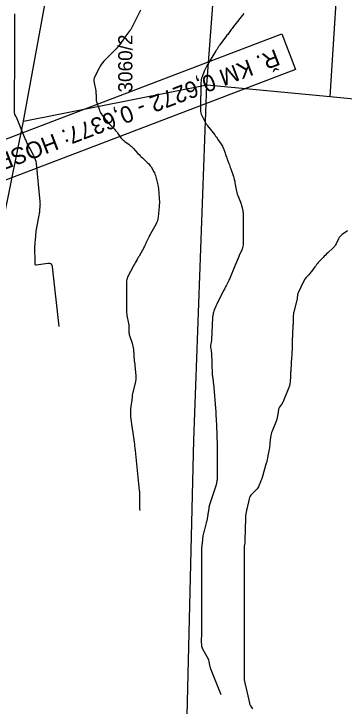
# Model space of a CAD drawing. Extents: x -534410 to -534262, y -1190162 to -1189584.
# Drawn here: x -534375.88 to -534356.09, y -1189988.43 to -1189946.91 of the extents above; entities that cross this region are included whole.
import ezdxf

# ---------------------------------------------------------------- set-up
doc = ezdxf.new("R2010")
doc.units = 0
for name, color, linetype in [('30', 7, 'Continuous'), ('31', 7, 'Continuous'), ('_N_text', 7, 'Continuous'), ('Hranice parcel', 7, 'Continuous'), ('Parcelní čísla', 7, 'Continuous')]:
    doc.layers.add(name, color=color, linetype=linetype)

msp = doc.modelspace()

# ---------------------------------------------------------------- linework, layer by layer
at = {"layer": '30'}
for points in [[(-534373.173, -1189965.667), (-534373.562, -1189962.09), (-534373.59, -1189961.98), (-534373.646, -1189961.907), (-534373.731, -1189961.871), (-534373.844, -1189961.871), (-534374.539, -1189961.971), (-534374.568, -1189961.971), (-534374.59, -1189961.962), (-534374.602, -1189961.942), (-534374.606, -1189961.913), (-534374.606, -1189961.776), (-534374.607, -1189961.742), (-534374.607, -1189961.708), (-534374.607, -1189961.674), (-534374.607, -1189961.64), (-534374.615, -1189961.047), (-534374.616, -1189960.946), (-534374.613, -1189960.845), (-534374.609, -1189960.743), (-534374.602, -1189960.642), (-534374.568, -1189960.238), (-534374.559, -1189960.137), (-534374.547, -1189960.036), (-534374.533, -1189959.936), (-534374.516, -1189959.836), (-534374.36, -1189958.978), (-534374.348, -1189958.911), (-534374.338, -1189958.844), (-534374.33, -1189958.777), (-534374.323, -1189958.709), (-534374.297, -1189958.438), (-534374.293, -1189958.371), (-534374.291, -1189958.303), (-534374.293, -1189958.235), (-534374.298, -1189958.168), (-534374.531, -1189955.886), (-534374.548, -1189955.772), (-534374.576, -1189955.662), (-534374.615, -1189955.556), (-534374.665, -1189955.453), (-534374.93, -1189954.968), (-534374.964, -1189954.906), (-534374.995, -1189954.843), (-534375.026, -1189954.78), (-534375.056, -1189954.716), (-534375.171, -1189954.458), (-534375.199, -1189954.394), (-534375.227, -1189954.329), (-534375.255, -1189954.264), (-534375.282, -1189954.199), (-534375.727, -1189953.111), (-534375.735, -1189953.092), (-534375.744, -1189953.072), (-534375.753, -1189953.054), (-534375.763, -1189953.035), (-534375.813, -1189952.942), (-534375.817, -1189952.933), (-534375.821, -1189952.923), (-534375.824, -1189952.914), (-534375.827, -1189952.904), (-534375.835, -1189952.864), (-534375.836, -1189952.854), (-534375.837, -1189952.844), (-534375.838, -1189952.834), (-534375.838, -1189952.824), (-534375.835, -1189952.777), (-534375.834, -1189952.765), (-534375.834, -1189952.754), (-534375.833, -1189952.743), (-534375.833, -1189952.732), (-534375.833, -1189950.957), (-534375.833, -1189950.946), (-534375.833, -1189950.935), (-534375.833, -1189950.924), (-534375.832, -1189950.912), (-534375.825, -1189950.784), (-534375.825, -1189950.773), (-534375.825, -1189950.763), (-534375.824, -1189950.753), (-534375.824, -1189950.743), (-534375.824, -1189948.946), (-534375.824, -1189948.936), (-534375.824, -1189948.926), (-534375.824, -1189948.916), (-534375.823, -1189948.905), (-534375.821, -1189948.863), (-534375.821, -1189948.844), (-534375.82, -1189948.826), (-534375.819, -1189948.778), (-534375.819, -1189948.759), (-534375.819, -1189948.75), (-534375.819, -1189946.939), (-534375.819, -1189946.92), (-534375.818, -1189946.901)], [(-534362.103, -1189946.892), (-534362.716, -1189947.667), (-534362.761, -1189947.724), (-534362.805, -1189947.782), (-534362.849, -1189947.841), (-534362.892, -1189947.899), (-534363.065, -1189948.135), (-534363.108, -1189948.194), (-534363.152, -1189948.253), (-534363.195, -1189948.312), (-534363.238, -1189948.37), (-534363.549, -1189948.789), (-534363.569, -1189948.817), (-534363.589, -1189948.845), (-534363.609, -1189948.873), (-534363.628, -1189948.902), (-534363.705, -1189949.016), (-534363.724, -1189949.045), (-534363.742, -1189949.073), (-534363.761, -1189949.103), (-534363.779, -1189949.132), (-534364.316, -1189950.027), (-534364.36, -1189950.104), (-534364.401, -1189950.183), (-534364.438, -1189950.264), (-534364.473, -1189950.346), (-534364.602, -1189950.678), (-534364.631, -1189950.762), (-534364.652, -1189950.848), (-534364.665, -1189950.934), (-534364.67, -1189951.023), (-534364.681, -1189951.753), (-534364.681, -1189951.768), (-534364.681, -1189951.782), (-534364.682, -1189951.797), (-534364.683, -1189951.812), (-534364.687, -1189951.87), (-534364.688, -1189951.884), (-534364.688, -1189951.899), (-534364.689, -1189951.913), (-534364.689, -1189951.928), (-534364.699, -1189952.666), (-534364.695, -1189952.754), (-534364.68, -1189952.84), (-534364.656, -1189952.923), (-534364.62, -1189953.003), (-534364.459, -1189953.321), (-534364.417, -1189953.399), (-534364.371, -1189953.475), (-534364.322, -1189953.549), (-534364.269, -1189953.621), (-534363.843, -1189954.172), (-534363.794, -1189954.237), (-534363.745, -1189954.303), (-534363.698, -1189954.37), (-534363.652, -1189954.437), (-534363.463, -1189954.719), (-534363.423, -1189954.783), (-534363.387, -1189954.849), (-534363.355, -1189954.917), (-534363.327, -1189954.987), (-534363.224, -1189955.272), (-534363.198, -1189955.344), (-534363.172, -1189955.415), (-534363.145, -1189955.486), (-534363.119, -1189955.557), (-534362.995, -1189955.881), (-534362.965, -1189955.959), (-534362.937, -1189956.037), (-534362.909, -1189956.116), (-534362.882, -1189956.194), (-534362.725, -1189956.655), (-534362.695, -1189956.75), (-534362.669, -1189956.846), (-534362.647, -1189956.944), (-534362.629, -1189957.042), (-534362.562, -1189957.449), (-534362.544, -1189957.54), (-534362.522, -1189957.63), (-534362.495, -1189957.719), (-534362.463, -1189957.807), (-534362.307, -1189958.205), (-534362.284, -1189958.267), (-534362.263, -1189958.33), (-534362.244, -1189958.394), (-534362.227, -1189958.458), (-534362.165, -1189958.716), (-534362.151, -1189958.78), (-534362.141, -1189958.845), (-534362.135, -1189958.911), (-534362.133, -1189958.977), (-534362.133, -1189960.661), (-534362.138, -1189960.752), (-534362.151, -1189960.841), (-534362.173, -1189960.928), (-534362.205, -1189961.014), (-534362.372, -1189961.408), (-534362.396, -1189961.465), (-534362.42, -1189961.521), (-534362.444, -1189961.577), (-534362.469, -1189961.634), (-534362.568, -1189961.858), (-534362.592, -1189961.915), (-534362.616, -1189961.971), (-534362.64, -1189962.028), (-534362.663, -1189962.085), (-534362.915, -1189962.711), (-534362.943, -1189962.778), (-534362.972, -1189962.843), (-534363.003, -1189962.908), (-534363.035, -1189962.972), (-534363.167, -1189963.227), (-534363.2, -1189963.29), (-534363.233, -1189963.354), (-534363.266, -1189963.418), (-534363.299, -1189963.482), (-534363.7, -1189964.269), (-534363.721, -1189964.311), (-534363.741, -1189964.354), (-534363.76, -1189964.397), (-534363.778, -1189964.441), (-534363.869, -1189964.67), (-534363.876, -1189964.688), (-534363.882, -1189964.705), (-534363.889, -1189964.722), (-534363.895, -1189964.74), (-534363.918, -1189964.81), (-534363.923, -1189964.827), (-534363.928, -1189964.845), (-534363.932, -1189964.863), (-534363.935, -1189964.881), (-534363.959, -1189965.014), (-534363.963, -1189965.042), (-534363.967, -1189965.07), (-534363.97, -1189965.099), (-534363.971, -1189965.127), (-534364.039, -1189966.468), (-534364.042, -1189966.506), (-534364.046, -1189966.544), (-534364.053, -1189966.582), (-534364.061, -1189966.62), (-534364.097, -1189966.77), (-534364.103, -1189966.807), (-534364.106, -1189966.845), (-534364.104, -1189966.882), (-534364.098, -1189966.92), (-534364.064, -1189967.073), (-534364.057, -1189967.111), (-534364.051, -1189967.149), (-534364.047, -1189967.188), (-534364.044, -1189967.227), (-534363.99, -1189968.538), (-534363.988, -1189968.569), (-534363.986, -1189968.6), (-534363.982, -1189968.631), (-534363.978, -1189968.661), (-534363.955, -1189968.798), (-534363.952, -1189968.821), (-534363.948, -1189968.845), (-534363.946, -1189968.868), (-534363.943, -1189968.891), (-534363.935, -1189968.985), (-534363.93, -1189969.032), (-534363.926, -1189969.079), (-534363.779, -1189970.793), (-534363.778, -1189970.802), (-534363.778, -1189970.81), (-534363.777, -1189970.819), (-534363.777, -1189970.828), (-534363.777, -1189970.862), (-534363.777, -1189970.87), (-534363.777, -1189970.879), (-534363.777, -1189970.887), (-534363.776, -1189970.896), (-534363.752, -1189971.308), (-534363.748, -1189971.38), (-534363.744, -1189971.451), (-534363.741, -1189971.523), (-534363.738, -1189971.594), (-534363.693, -1189972.768), (-534363.693, -1189972.781), (-534363.692, -1189972.793), (-534363.692, -1189972.806), (-534363.693, -1189972.818), (-534363.694, -1189972.868), (-534363.694, -1189972.893), (-534363.694, -1189972.918), (-534363.694, -1189974.774), (-534363.694, -1189974.785), (-534363.695, -1189974.796), (-534363.696, -1189974.806), (-534363.697, -1189974.817), (-534363.703, -1189974.86), (-534363.706, -1189974.881), (-534363.71, -1189974.903), (-534363.734, -1189975.046), (-534363.739, -1189975.073), (-534363.745, -1189975.1), (-534363.752, -1189975.126), (-534363.761, -1189975.153), (-534364.143, -1189976.306), (-534364.159, -1189976.358), (-534364.173, -1189976.411), (-534364.184, -1189976.465), (-534364.193, -1189976.519), (-534364.224, -1189976.736), (-534364.232, -1189976.79), (-534364.24, -1189976.844), (-534364.249, -1189976.898), (-534364.258, -1189976.953), (-534364.318, -1189977.295), (-534364.332, -1189977.37), (-534364.349, -1189977.445), (-534364.367, -1189977.519), (-534364.388, -1189977.592), (-534364.482, -1189977.907), (-534364.503, -1189977.984), (-534364.521, -1189978.062), (-534364.536, -1189978.14), (-534364.548, -1189978.219), (-534364.604, -1189978.648), (-534364.615, -1189978.747), (-534364.623, -1189978.845), (-534364.628, -1189978.943), (-534364.629, -1189979.042), (-534364.629, -1189982.62), (-534364.629, -1189982.732), (-534364.63, -1189982.844), (-534364.631, -1189982.957), (-534364.632, -1189983.069), (-534364.641, -1189983.692), (-534364.641, -1189983.717), (-534364.641, -1189983.743), (-534364.641, -1189983.768), (-534364.641, -1189983.794), (-534364.641, -1189983.895), (-534364.641, -1189983.921), (-534364.641, -1189983.946), (-534364.642, -1189983.972), (-534364.642, -1189983.997), (-534364.651, -1189984.62), (-534364.645, -1189984.731), (-534364.626, -1189984.838), (-534364.593, -1189984.941), (-534364.546, -1189985.041), (-534364.243, -1189985.593), (-534364.233, -1189985.613), (-534364.225, -1189985.633), (-534364.218, -1189985.654), (-534364.213, -1189985.675), (-534364.195, -1189985.761), (-534364.19, -1189985.782), (-534364.186, -1189985.804), (-534364.182, -1189985.825), (-534364.177, -1189985.847), (-534364.147, -1189985.998), (-534364.14, -1189986.03), (-534364.131, -1189986.062), (-534364.121, -1189986.093), (-534364.11, -1189986.124), (-534363.477, -1189987.725)]]:
    msp.add_lwpolyline(points, dxfattribs=at)
at = {"layer": '31'}
for points in [[(-534368.288, -1189946.694), (-534368.743, -1189947.601), (-534368.785, -1189947.681), (-534368.83, -1189947.76), (-534368.879, -1189947.836), (-534368.931, -1189947.911), (-534369.162, -1189948.229), (-534369.206, -1189948.291), (-534369.251, -1189948.352), (-534369.295, -1189948.414), (-534369.34, -1189948.475), (-534369.593, -1189948.825), (-534369.6, -1189948.835), (-534369.607, -1189948.844), (-534369.615, -1189948.854), (-534369.622, -1189948.863), (-534369.654, -1189948.9), (-534369.661, -1189948.909), (-534369.669, -1189948.919), (-534369.677, -1189948.928), (-534369.684, -1189948.937), (-534369.725, -1189948.989), (-534369.734, -1189949.001), (-534369.744, -1189949.012), (-534369.754, -1189949.023), (-534369.764, -1189949.034), (-534370.479, -1189949.747), (-534370.565, -1189949.84), (-534370.643, -1189949.94), (-534370.712, -1189950.045), (-534370.773, -1189950.157), (-534371.023, -1189950.665), (-534371.059, -1189950.756), (-534371.079, -1189950.849), (-534371.084, -1189950.944), (-534371.072, -1189951.041), (-534370.977, -1189951.526), (-534370.968, -1189951.578), (-534370.962, -1189951.631), (-534370.958, -1189951.684), (-534370.957, -1189951.738), (-534370.957, -1189951.951), (-534370.955, -1189952.004), (-534370.949, -1189952.057), (-534370.938, -1189952.109), (-534370.924, -1189952.16), (-534370.755, -1189952.682), (-534370.726, -1189952.761), (-534370.689, -1189952.837), (-534370.646, -1189952.909), (-534370.596, -1189952.978), (-534370.383, -1189953.244), (-534370.329, -1189953.311), (-534370.274, -1189953.376), (-534370.217, -1189953.439), (-534370.159, -1189953.502), (-534369.853, -1189953.828), (-534369.799, -1189953.887), (-534369.747, -1189953.949), (-534369.697, -1189954.011), (-534369.649, -1189954.076), (-534369.46, -1189954.336), (-534369.41, -1189954.399), (-534369.356, -1189954.458), (-534369.298, -1189954.512), (-534369.235, -1189954.561), (-534368.974, -1189954.75), (-534368.91, -1189954.799), (-534368.849, -1189954.85), (-534368.79, -1189954.905), (-534368.734, -1189954.963), (-534368.447, -1189955.273), (-534368.38, -1189955.343), (-534368.312, -1189955.413), (-534368.242, -1189955.481), (-534368.171, -1189955.548), (-534367.864, -1189955.833), (-534367.806, -1189955.891), (-534367.753, -1189955.953), (-534367.705, -1189956.019), (-534367.661, -1189956.088), (-534367.498, -1189956.374), (-534367.46, -1189956.447), (-534367.427, -1189956.522), (-534367.399, -1189956.599), (-534367.377, -1189956.678), (-534367.26, -1189957.166), (-534367.236, -1189957.273), (-534367.218, -1189957.381), (-534367.204, -1189957.489), (-534367.194, -1189957.598), (-534367.166, -1189958.035), (-534367.161, -1189958.144), (-534367.161, -1189958.253), (-534367.165, -1189958.363), (-534367.173, -1189958.472), (-534367.232, -1189959.084), (-534367.25, -1189959.206), (-534367.28, -1189959.324), (-534367.323, -1189959.439), (-534367.378, -1189959.549), (-534367.684, -1189960.096), (-534367.713, -1189960.148), (-534367.742, -1189960.201), (-534367.769, -1189960.255), (-534367.796, -1189960.308), (-534367.93, -1189960.58), (-534367.943, -1189960.606), (-534367.955, -1189960.632), (-534367.968, -1189960.659), (-534367.98, -1189960.685), (-534368.028, -1189960.791), (-534368.04, -1189960.818), (-534368.053, -1189960.844), (-534368.066, -1189960.87), (-534368.08, -1189960.896), (-534368.38, -1189961.438), (-534368.408, -1189961.487), (-534368.435, -1189961.536), (-534368.463, -1189961.586), (-534368.491, -1189961.635), (-534368.603, -1189961.831), (-534368.63, -1189961.88), (-534368.657, -1189961.93), (-534368.684, -1189961.979), (-534368.71, -1189962.029), (-534369.064, -1189962.709), (-534369.095, -1189962.778), (-534369.116, -1189962.849), (-534369.13, -1189962.922), (-534369.134, -1189962.997), (-534369.134, -1189963.377), (-534369.134, -1189963.606), (-534369.134, -1189964.159), (-534369.134, -1189964.388), (-534369.134, -1189964.692), (-534369.132, -1189964.768), (-534369.127, -1189964.844), (-534369.117, -1189964.919), (-534369.104, -1189964.994), (-534369.006, -1189965.488), (-534368.996, -1189965.546), (-534368.988, -1189965.606), (-534368.984, -1189965.665), (-534368.983, -1189965.725), (-534368.983, -1189965.964), (-534368.98, -1189966.024), (-534368.973, -1189966.082), (-534368.961, -1189966.14), (-534368.945, -1189966.198), (-534368.794, -1189966.654), (-534368.766, -1189966.75), (-534368.743, -1189966.847), (-534368.727, -1189966.945), (-534368.716, -1189967.044), (-534368.665, -1189967.714), (-534368.663, -1189967.739), (-534368.661, -1189967.763), (-534368.657, -1189967.787), (-534368.654, -1189967.812), (-534368.638, -1189967.909), (-534368.634, -1189967.933), (-534368.631, -1189967.958), (-534368.628, -1189967.982), (-534368.626, -1189968.007), (-534368.571, -1189968.623), (-534368.566, -1189968.733), (-534368.571, -1189968.843), (-534368.585, -1189968.952), (-534368.608, -1189969.06), (-534368.793, -1189969.764), (-534368.795, -1189969.776), (-534368.797, -1189969.789), (-534368.797, -1189969.801), (-534368.796, -1189969.813), (-534368.788, -1189969.862), (-534368.787, -1189969.874), (-534368.787, -1189969.886), (-534368.787, -1189969.898), (-534368.788, -1189969.911), (-534368.881, -1189970.605), (-534368.893, -1189970.725), (-534368.897, -1189970.844), (-534368.893, -1189970.964), (-534368.881, -1189971.084), (-534368.784, -1189971.796), (-534368.771, -1189971.893), (-534368.675, -1189972.602), (-534368.659, -1189972.723), (-534368.644, -1189972.845), (-534368.63, -1189972.966), (-534368.617, -1189973.088), (-534368.365, -1189975.498), (-534368.36, -1189975.555), (-534368.356, -1189975.613), (-534368.354, -1189975.67), (-534368.353, -1189975.728), (-534368.353, -1189976.526), (-534368.353, -1189976.544), (-534368.354, -1189976.574), (-534368.354, -1189976.58), (-534368.353, -1189976.585), (-534368.352, -1189976.591), (-534368.351, -1189976.597), (-534368.325, -1189976.696)], [(-534355.894, -1189959.915), (-534356.21, -1189960.143), (-534356.274, -1189960.195), (-534356.331, -1189960.254), (-534356.379, -1189960.32), (-534356.42, -1189960.392), (-534356.567, -1189960.694), (-534356.607, -1189960.767), (-534356.653, -1189960.835), (-534356.705, -1189960.899), (-534356.764, -1189960.958), (-534357.071, -1189961.241), (-534357.142, -1189961.308), (-534357.211, -1189961.376), (-534357.28, -1189961.446), (-534357.346, -1189961.517), (-534357.635, -1189961.829), (-534357.688, -1189961.889), (-534357.74, -1189961.95), (-534357.79, -1189962.012), (-534357.839, -1189962.075), (-534358.051, -1189962.358), (-534358.09, -1189962.408), (-534358.13, -1189962.458), (-534358.17, -1189962.508), (-534358.212, -1189962.556), (-534358.379, -1189962.748), (-534358.419, -1189962.798), (-534358.455, -1189962.849), (-534358.488, -1189962.903), (-534358.518, -1189962.959), (-534358.846, -1189963.644), (-534358.86, -1189963.678), (-534358.871, -1189963.712), (-534358.879, -1189963.747), (-534358.883, -1189963.783), (-534358.895, -1189963.929), (-534358.899, -1189963.965), (-534358.904, -1189964.002), (-534358.911, -1189964.037), (-534358.92, -1189964.073), (-534359.093, -1189964.701), (-534359.111, -1189964.773), (-534359.124, -1189964.846), (-534359.132, -1189964.919), (-534359.137, -1189964.993), (-534359.144, -1189965.291), (-534359.146, -1189965.365), (-534359.149, -1189965.44), (-534359.152, -1189965.514), (-534359.156, -1189965.588), (-534359.185, -1189966.157), (-534359.189, -1189966.225), (-534359.192, -1189966.294), (-534359.194, -1189966.363), (-534359.196, -1189966.432), (-534359.204, -1189966.715), (-534359.206, -1189966.78), (-534359.208, -1189966.844), (-534359.21, -1189966.909), (-534359.212, -1189966.974), (-534359.22, -1189967.233), (-534359.223, -1189967.298), (-534359.226, -1189967.363), (-534359.229, -1189967.428), (-534359.234, -1189967.492), (-534359.288, -1189968.285), (-534359.291, -1189968.341), (-534359.294, -1189968.397), (-534359.297, -1189968.453), (-534359.299, -1189968.509), (-534359.308, -1189968.748), (-534359.31, -1189968.796), (-534359.313, -1189968.844), (-534359.318, -1189968.892), (-534359.324, -1189968.94), (-534359.348, -1189969.132), (-534359.356, -1189969.179), (-534359.366, -1189969.226), (-534359.38, -1189969.272), (-534359.396, -1189969.317), (-534359.698, -1189970.065), (-534359.722, -1189970.12), (-534359.749, -1189970.173), (-534359.778, -1189970.226), (-534359.81, -1189970.276), (-534359.974, -1189970.519), (-534359.991, -1189970.548), (-534360.005, -1189970.578), (-534360.015, -1189970.61), (-534360.022, -1189970.643), (-534360.041, -1189970.777), (-534360.046, -1189970.811), (-534360.051, -1189970.844), (-534360.056, -1189970.878), (-534360.062, -1189970.911), (-534360.099, -1189971.123), (-534360.108, -1189971.169), (-534360.12, -1189971.215), (-534360.134, -1189971.26), (-534360.15, -1189971.304), (-534360.408, -1189971.939), (-534360.44, -1189972.025), (-534360.465, -1189972.113), (-534360.483, -1189972.203), (-534360.496, -1189972.294), (-534360.532, -1189972.661), (-534360.542, -1189972.753), (-534360.554, -1189972.844), (-534360.569, -1189972.935), (-534360.586, -1189973.025), (-534360.748, -1189973.832), (-534360.75, -1189973.838), (-534360.752, -1189973.844), (-534360.758, -1189973.857), (-534360.76, -1189973.866), (-534361.009, -1189974.716), (-534361.029, -1189974.78), (-534361.05, -1189974.844), (-534361.072, -1189974.907), (-534361.096, -1189974.97), (-534361.194, -1189975.22), (-534361.221, -1189975.28), (-534361.255, -1189975.337), (-534361.294, -1189975.39), (-534361.339, -1189975.438), (-534361.618, -1189975.712), (-534361.675, -1189975.776), (-534361.722, -1189975.846), (-534361.757, -1189975.922), (-534361.782, -1189976.005), (-534361.921, -1189976.609), (-534361.926, -1189976.633), (-534361.931, -1189976.656), (-534361.936, -1189976.68), (-534361.941, -1189976.703), (-534361.959, -1189976.797), (-534361.963, -1189976.821), (-534361.967, -1189976.845), (-534361.97, -1189976.868), (-534361.973, -1189976.892), (-534361.99, -1189977.035), (-534361.993, -1189977.067), (-534361.995, -1189977.098), (-534361.997, -1189977.13), (-534361.999, -1189977.162), (-534362.036, -1189978.475), (-534362.037, -1189978.512), (-534362.04, -1189978.55), (-534362.043, -1189978.587), (-534362.048, -1189978.623), (-534362.068, -1189978.771), (-534362.073, -1189978.808), (-534362.076, -1189978.845), (-534362.078, -1189978.882), (-534362.079, -1189978.919), (-534362.079, -1189986.774), (-534362.078, -1189986.809), (-534362.075, -1189986.844), (-534362.07, -1189986.879), (-534362.064, -1189986.914), (-534362.035, -1189987.052), (-534362.027, -1189987.087), (-534362.02, -1189987.121), (-534362.012, -1189987.156), (-534362.004, -1189987.191), (-534361.763, -1189988.255), (-534361.751, -1189988.299), (-534361.736, -1189988.34), (-534361.716, -1189988.38), (-534361.693, -1189988.419), (-534361.578, -1189988.591)]]:
    msp.add_lwpolyline(points, dxfattribs=at)
at = {"layer": '_N_text'}
msp.add_lwpolyline([(-534358.995, -1189950.253), (-534388.393, -1189961.469), (-534389.213, -1189959.319), (-534359.815, -1189948.103)], close=True, dxfattribs=at)
at = {"layer": 'Hranice parcel'}
for p, q in [((-534375.31, -1189953.34), (-534373.8, -1189945.18)), ((-534375.31, -1189953.34), (-534364.31, -1189951.16)), ((-534364.31, -1189951.16), (-534356.92, -1189951.87)), ((-534356.92, -1189951.87), (-534353.94, -1189952.16))]:
    msp.add_line(p, q, dxfattribs=at)
for points in [[(-534364.31, -1189951.16), (-534363.86, -1189945.04), (-534362.87, -1189931.95)], [(-534356.92, -1189951.87), (-534356.3, -1189942.12), (-534356.23, -1189940.98)], [(-534365.84, -1190003.05), (-534365.09, -1189972.48), (-534364.31, -1189951.16)], [(-534377.74, -1189975.71), (-534377.67, -1189972.94), (-534376.87, -1189961.07), (-534375.31, -1189953.34)]]:
    msp.add_lwpolyline(points, dxfattribs=at)

# ---------------------------------------------------------------- texts
at = {"layer": '_N_text'}
msp.add_text('Ř. KM 0,6272 - 0,6377: HOSPODÁŘSKÝ MOST', height=1, rotation=200.9032, dxfattribs=at).set_placement((-534360.199, -1189948.996))
at = {"layer": 'Parcelní čísla'}
msp.add_text('3060/2', height=0.85, rotation=90, dxfattribs=at).set_placement((-534368.777, -1189951.624))

doc.saveas('drawing.dxf')
